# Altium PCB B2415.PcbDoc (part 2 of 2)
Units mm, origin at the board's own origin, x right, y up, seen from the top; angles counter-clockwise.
Board outline 20.32 x 48.65 mm, 4 copper layers (Top Layer, Internal 1, Internal 2, Bottom Layer), stack 0.62 mm thick; 96 components, 71 nets, 432 pads, 386 vias.
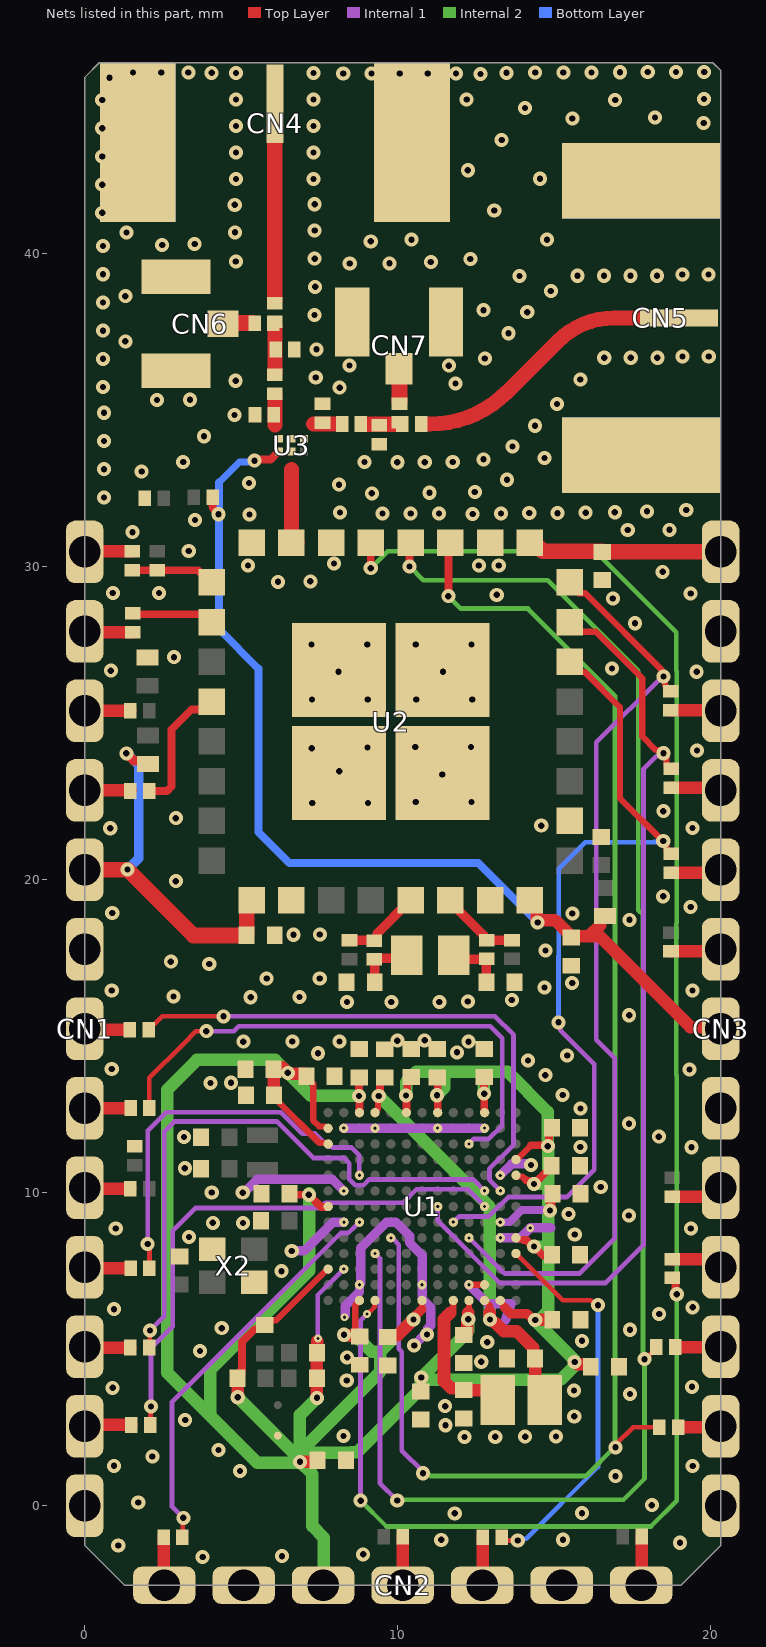
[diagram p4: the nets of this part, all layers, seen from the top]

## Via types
v1: diameter 0.45, hole 0.2, Top Layer to Bottom Layer, tented both sides, 351 vias
v2: diameter 0.25, hole 0.1, Top Layer to Internal 1, tented top, 35 vias

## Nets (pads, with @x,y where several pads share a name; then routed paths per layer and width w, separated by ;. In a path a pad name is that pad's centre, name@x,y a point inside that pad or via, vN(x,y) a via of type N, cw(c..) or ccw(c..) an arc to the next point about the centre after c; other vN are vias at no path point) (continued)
GND: C1.1 C2.1 C3.1 C4.1 C6.2 C7.1 C8.2 C9.2 C10.1 C17.1 C18.1 C19.1 C20.1 C21.1 C22.1 C23.1 C24.1 C25.1 C26.1 C27.1 C29.1 C30.1 C31.1 C38.1 C39.1 C40.1 C41.1 C42.1 C43.1 C44.1 C45.1 C46.1 CN1.6 CN1.13 CN2.2 CN2.6 CN3.1 CN3.6 CN3.12 CN4.2 CN4.3 CN4.4 CN4.5 CN5.2 CN5.3 CN5.4 CN5.5 CN6.2 CN6.3 CN7.2 CN7.3 R19.2 R30.1 R37.1 R38.1 R45.1 R46.1 R51.1 SB38.2 U1.B2 U1.B4 U1.B8 U1.B11 U1.E12 U1.F2 U1.H2 U1.J12 U1.M3 U1.M7 U1.M10 U1.M11 U2.10 U2.15 U2.18 U2.26 U2.30 U2.32 U2.33 U2.34 U2.35 U2.36 U3.2 X2.2 X2.4 | length 24.1
  Top Layer w0.2: U1.M10@12.293,7.038 12.317,7.062 U1.M11@12.778,7.062
  Internal 1 w0.3: v1@5.07,10.074 5.111,10.033 5.119,10.033 5.517,10.432 7.908,10.432 v2(8.276,10.064) ; v1(6.614,8.144) 7.013,8.144 7.931,9.062 v2(8.28,9.062) ; v2(8.276,12.066) 12.759,12.066 v2@12.761,12.068 ; v2@8.327,6.09 8.327,6.38 8.779,6.831 v2(8.779,7.063) 8.825,7.11 8.825,8.243 9.642,9.061 9.943,9.061 10.383,8.621 10.383,8.4 10.787,7.996 10.787,6.616 11.057,6.346 11.057,5.76 10.963,5.666 10.963,5.504 v1(10.934,5.476) 10.905,5.447 10.845,5.447 10.527,5.129 v1(10.527,5.124) ; v2(12.273,7.062) 12.878,6.457 13.626,6.457 13.442,5.923 ; v2(13.276,10.559) 13.642,10.925 v1@14.29,10.925 ; v2(13.28,8.564) 13.923,8.564 v2(14.238,8.879) 14.896,8.879
  other v1: 3.769,-1.639 6.303,-1.611 8.895,-1.552 1.071,-1.269 19.022,-1.182 11.393,-1.087 15.284,-1.086 11.824,-0.242 15.893,-0.237 18.12,0.02 1.709,0.102 16.959,0.945 4.964,1.111 0.938,1.277 19.425,1.273 2.161,1.573 4.273,1.779 12.132,2.201 13.118,2.202 14.074,2.209 15.059,2.21 8.27,2.233 11.531,2.573 3.209,2.741 15.643,2.857 11.516,3.182 17.425,3.57 15.633,3.683 0.894,3.769 19.408,3.8 8.373,4.001 12.67,4.601 8.385,4.744 3.681,4.948 12.863,5.229 15.891,5.269 17.421,5.624 4.379,5.674 18.355,6.126 0.932,6.281 19.426,6.342 6.287,7.495 3.331,8.59 15.657,8.667 0.992,8.863 19.367,8.862 4.093,9.041 5.055,9.038 17.385,9.272 15.463,9.32 5.049,10.005 4.059,10.011 16.488,10.189 3.198,10.786 14.26,10.887 15.835,11.461 19.386,11.456 3.175,11.783 18.344,11.795 17.388,12.21 15.839,12.693 15.271,13.126 4.018,13.507 4.67,13.518 14.719,13.759 19.321,13.941 0.864,13.957 14.16,14.231 15.416,14.386 7.452,14.46 11.897,14.488 5.068,14.831 8.144,14.834 12.261,14.829 6.635,14.837 9.988,14.862 10.863,14.874 17.396,15.674 8.38,16.099 9.797,16.094 11.331,16.099 12.241,16.113 13.646,16.159 5.303,16.249 2.833,16.277 6.86,16.257 0.864,16.467 19.417,16.467 14.695,16.563 15.574,16.705 5.814,16.85 7.509,16.849 3.978,17.313 2.752,17.387 14.724,17.741 6.669,18.246 7.513,18.251 17.408,18.723 0.879,18.942 15.579,18.925 19.361,19.133 18.482,19.473 2.911,19.957 0.815,21.65 19.42,21.654 14.588,21.731 2.91,21.972 18.488,22.194 7.267,22.458 9.052,22.458 10.577,22.487 12.362,22.487 11.428,23.37 8.133,23.467 19.564,24.136 7.253,24.207 9.033,24.227 10.56,24.247 12.345,24.247 7.261,25.763 9.046,25.763 10.594,25.763 12.379,25.763 8.112,26.646 11.445,26.646 19.553,26.65 0.835,26.685 16.846,26.757 2.855,27.116 7.244,27.524 9.029,27.524 10.577,27.524 12.362,27.524 17.583,28.199 16.876,28.99 13.164,29.107 19.361,29.149 0.897,29.163 2.371,29.164 6.175,29.522 7.208,29.538 18.467,29.843 5.22,30.042 12.592,30.049 13.229,30.045 7.967,30.109 3.323,30.51 1.527,31.109 17.352,31.182 18.684,31.185 3.525,31.502 5.268,31.677 12.395,31.689 9.515,31.709 10.416,31.709 11.317,31.709 13.303,31.707 14.204,31.719 15.105,31.718 8.16,31.735 16.007,31.734 16.938,31.746 17.965,31.775 19.219,31.821 0.619,32.222 9.174,32.351 11.017,32.37 12.464,32.393 8.125,32.629 5.249,32.683 13.489,32.786 1.819,33.05 0.619,33.123 8.938,33.349 9.988,33.344 10.864,33.347 3.145,33.356 11.76,33.355 12.744,33.436 14.692,33.477 13.672,33.851 0.619,34.024 3.812,34.176 14.388,34.51 4.788,34.852 0.619,34.925 15.091,35.208 2.307,35.331 3.366,35.342 8.146,35.728 0.586,35.746 11.85,35.86 4.823,35.947 15.837,35.985 7.383,36.051 8.461,36.435 11.634,36.429 0.586,36.648 12.784,36.659 16.601,36.684 17.448,36.684 18.296,36.684 19.101,36.723 19.939,36.724 7.403,36.952 1.298,37.208 13.538,37.467 0.586,37.549 7.342,38.047 14.14,38.14 12.741,38.203 0.586,38.45 1.298,38.65 14.894,38.814 7.362,38.948 13.891,39.299 15.747,39.304 16.594,39.304 17.442,39.304 18.289,39.304 19.094,39.343 19.932,39.344 0.586,39.351 8.469,39.694 9.739,39.699 11.059,39.742 4.828,39.757 7.347,39.849 12.321,39.84 0.586,40.253 2.475,40.289 3.511,40.317 9.14,40.402 10.443,40.455 14.772,40.456 1.336,40.688 4.803,40.69 7.347,40.751 0.56,41.313 13.085,41.386 4.794,41.571 7.346,41.588 0.56,42.215 4.832,42.392 7.307,42.393 14.548,42.404 12.242,42.675 0.56,43.116 4.832,43.239 7.307,43.241 13.323,43.645 0.56,44.017 4.832,44.086 7.307,44.088 19.778,44.181 15.582,44.329 18.222,44.361 14.071,44.663 0.56,44.919 16.95,44.917 4.832,44.934 7.307,44.935 12.204,44.937 19.786,44.953 0.795,45.632 8.26,45.763 9.161,45.763 10.063,45.763 10.964,45.763 11.865,45.763 12.649,45.751 4.055,45.787 4.832,45.781 7.307,45.783 13.48,45.788 1.543,45.797 2.444,45.797 3.311,45.799 14.392,45.801 15.293,45.801 16.195,45.801 17.101,45.807 17.991,45.811 18.893,45.811 19.794,45.811
  other v2: 8.297,6.024 10.777,7.063 9.275,12.062 11.278,12.066 12.777,12.066
JTCK: R9.2 U2.2 | length 2.7
  Top Layer w0.25: R9.2@1.443,28.489 3.755,28.489 U2.2@4.031,28.213
JTDI: R11.2 U2.4 | length 4.1
  Top Layer w0.25: R11.2@2.057,22.84 2.631,22.84 2.777,22.986 2.777,24.808 3.418,25.448 3.891,25.448 U2.4@3.994,25.551
JTMS: R8.2 R34.1 U2.1 | length 2.7
  Top Layer w0.25: R8.2@1.521,29.895 3.618,29.895 3.708,29.804 3.764,29.804 4.031,29.538 U2.1@4.031,29.483
LPUART1_RX: R2.1 U1.G8 U2.23 | length 30.9
  Top Layer w0.2: U2.23@15.461,28.213 15.749,27.924 16.333,27.924 17.813,26.444 17.813,24.585 18.253,24.146 18.325,24.146 18.426,24.045 v1(18.494,24.045) 18.494,23.977 18.588,23.883 18.588,23.647 18.714,23.522 R2.1@18.762,23.522
  Internal 1 w0.15: v2(11.28,9.562) 11.28,9.106 13.269,7.117 16.638,7.117 17.857,8.335 17.857,23.545 18.258,23.945 18.313,23.945 18.413,24.045 v1(18.494,24.045)
"LPUART1_TX/ HostWakeup": R3.1 U1.H9 U2.22 | length 26.6
  Top Layer w0.2: U2.22@15.461,26.943 15.762,26.642 15.972,26.642 17.102,25.512 17.102,22.604 18.463,21.243 v1(18.486,21.243) 18.486,21.175 18.59,21.071 18.59,20.929 18.657,20.862 R3.1@18.753,20.862
  Internal 1 w0.15: v2@11.806,9.086 11.966,9.246 12.914,9.246 13.533,9.864 15.407,9.864 16.282,10.739 16.282,14.114 15.197,15.198 15.197,15.389 v1(15.14,15.446)
  Bottom Layer w0.15: v1(15.14,15.446) 15.14,17.563 15.144,17.567 15.144,20.361 15.987,21.205 18.172,21.205 18.18,21.213 18.456,21.213 v1(18.486,21.243)
  other v2: 11.776,9.065
NetC6_1: C6.1 R22.2 X3.2 | length 1.7
  Top Layer w0.3: R22.2@9.248,17.46 9.281,17.493 10.284,17.493 X3.2@10.294,17.502 ; C6.1@9.267,16.729 9.267,17.41 R22.2@9.271,17.41
NetC7_2: C7.2 R23.2 X3.1 | length 1.9
  Top Layer w0.3: X3.1@11.793,17.593 11.919,17.466 R23.2@12.845,17.466 ; C7.2@12.832,16.734 12.832,17.423 12.854,17.444 R23.2@12.916,17.444
NetC40_2: C40.2 L1.1 U1.N9 | length 4.3
  Top Layer w0.2: 11.678,6.165 11.778,6.265 U1.N9@11.778,6.562
  Top Layer w0.3: L1.1@12.872,3.692 L1.1@12.923,3.641
  Top Layer w0.4: 11.678,6.165 11.48,5.966 11.48,3.984 11.714,3.75 12.058,3.75 12.115,3.692 L1.1@12.872,3.692
NetC44_2: C44.2 C45.2 L1.2 U1.A4 U1.N11 | length 13.9
  Top Layer w0.2: U1.A4@9.278,12.562 9.278,12.589 9.369,12.68 v1@9.369,13.095 ; U1.N11@12.778,6.562 12.948,6.392 12.948,6.185
  Top Layer w0.25: v1@9.395,13.149 9.434,13.188 9.434,13.557 9.55,13.673 C45.2@9.612,13.673
  Top Layer w0.4: v1(12.948,5.955) 12.948,6.185 ; v1@13.108,5.855 13.383,5.579 13.804,5.579 14.339,5.044 14.339,4.761 C44.2@14.394,4.706 14.394,3.685 L1.2@14.698,3.381
  Internal 2 w0.4: v1(9.395,13.095) 12.948,9.541 v1(12.948,5.955)
NetCN1_1: CN1.1 R8.1 | length 1.5
  Top Layer w0.4: CN1.1@0.015,30.495 R8.1@1.521,30.495
NetCN1_2: CN1.2 R9.1 | length 1.5
  Top Layer w0.4: CN1.2@0.025,27.915 R9.1@1.532,27.915
NetCN1_3: CN1.3 R10.1 | length 1.5
  Top Layer w0.25: R10.1@1.455,25.4 R10.1@1.474,25.419
  Top Layer w0.4: CN1.3@0,25.4 R10.1@1.455,25.4
NetCN1_4: CN1.4 R11.1 | length 1.5
  Top Layer w0.25: R11.1@1.467,22.86 R11.1@1.497,22.83
  Top Layer w0.4: CN1.4@0,22.86 R11.1@1.467,22.86
NetCN1_7: CN1.7 R12.1 | length 1.3
  Top Layer w0.25: CN1.7@0.146,15.185 CN1.7@0.172,15.211
  Top Layer w0.4: CN1.7@0.172,15.211 R12.1@1.445,15.211
NetCN1_8: CN1.8 R13.1 | length 1.3
  Top Layer w0.3: CN1.8@0.202,12.711 CN1.8@0.204,12.708
  Top Layer w0.4: CN1.8@0.204,12.708 R13.1@1.464,12.708
NetCN1_9: CN1.9 R14.1 | length 1.2
  Top Layer w0.3: CN1.9@0.304,10.144 CN1.9@0.313,10.134
  Top Layer w0.4: CN1.9@0.313,10.134 R14.1@1.457,10.134
NetCN1_10: CN1.10 R15.1 | length 1.3
  Top Layer w0.3: CN1.10@0.174,7.586 CN1.10@0.181,7.593
  Top Layer w0.4: CN1.10@0.181,7.593 R15.1@1.469,7.593
NetCN1_11: CN1.11 R16.1 | length 1.4
  Top Layer w0.3: CN1.11@0.063,5.047 CN1.11@0.072,5.056
  Top Layer w0.4: CN1.11@0.072,5.056 R16.1@1.459,5.056
NetCN1_12: CN1.12 R17.1 | length 1.4
  Top Layer w0.25: R17.1@1.485,2.582 R17.1@1.488,2.579
  Top Layer w0.4: CN1.12@0.044,2.582 R17.1@1.485,2.582
NetCN2_1: CN2.1 R20.1 | length 1.6
  Top Layer w0.4: CN2.1@2.521,-2.618 R20.1@2.521,-0.983
NetCN2_4: CN2.4 R21.1 | length 1.6
  Top Layer w0.4: CN2.4@10.143,-2.573 10.159,-2.556 R21.1@10.159,-0.987
NetCN2_5: CN2.5 R28.1 | length 1.5
  Top Layer w0.4: CN2.5@12.72,-2.478 R28.1@12.72,-0.98
NetCN2_7: CN2.7 R27.1 | length 1.5
  Top Layer w0.4: R27.1@17.792,-0.981 17.792,-2.469 CN2.7@17.834,-2.511
NetCN3_2: CN3.2 R26.2 | length 1.4
  Top Layer w0.4: R26.2@18.984,2.515 20.342,2.515 CN3.2@20.351,2.523
NetCN3_3: CN3.3 R7.2 | length 1.6
  Top Layer w0.4: R7.2@18.865,5.071 20.396,5.071 CN3.3@20.413,5.054
NetCN3_4: CN3.4 R6.2 | length 1.7
  Top Layer w0.4: R6.2@18.779,7.88 19.965,7.88 CN3.4@20.347,7.499
NetCN3_5: CN3.5 R5.2 | length 1.6
  Top Layer w0.4: R5.2@18.77,9.877 19.948,9.877 CN3.5@20.281,10.21
NetCN3_8: CN3.8 R4.2 | length 1.6
  Top Layer w0.25: CN3.8@20.292,17.717 CN3.8@20.33,17.755
  Top Layer w0.4: R4.2@18.733,17.717 CN3.8@20.292,17.717
NetCN3_9: CN3.9 R3.2 | length 1.5
  Top Layer w0.25: CN3.9@20.165,20.229 CN3.9@20.199,20.263
  Top Layer w0.4: R3.2@18.74,20.229 CN3.9@20.165,20.229
NetCN3_10: CN3.10 R2.2 | length 1.6
  Top Layer w0.25: CN3.10@20.223,22.947 CN3.10@20.299,22.872
  Top Layer w0.4: R2.2@18.738,22.947 CN3.10@20.223,22.947
NetCN3_11: CN3.11 R1.2 | length 1.6
  Top Layer w0.25: CN3.11@20.352,25.426 CN3.11@20.368,25.442
  Top Layer w0.4: R1.2@18.731,25.426 CN3.11@20.352,25.426
NetCN4_1: CN4.1 R49.2 | length 6.3
  Top Layer w0.5: R49.2@6.076,38.5 6.076,44.783 6.076,44.786 6.076,44.794 CN4.1@6.076,44.798
NetCN5_1: CN5.1 R50.2 | length 9.3
  Top Layer w0.48: R50.2@10.818,34.567 11.036,34.567 ccw(c11.036,38.034) 13.489,35.583 15.119,37.213 cw(c16.915,35.417) 16.915,37.957 18.99,37.957 CN5.1@18.991,37.956
NetCN6_1: CN6.1 R39.1 | length 1
  Top Layer w0.5: CN6.1@4.428,37.792 R39.1@5.357,37.792
  Top Layer w0.52: CN6.1@4.395,37.826 CN6.1@4.428,37.792
NetCN7_1: CN7.1 R47.1 | length 1.1
  Top Layer w0.5: CN7.1@10.043,36.328 10.042,36.327 10.057,36.311 R47.1@10.057,35.282
NetJ?_S1: 
NetR22_1: R22.1 R31.2 U2.13 | length 2.4
  Top Layer w0.3: R31.2@8.459,18.068 9.226,18.068 R22.1@9.249,18.045 ; R22.1@9.348,18.11 9.348,18.291 U2.13@10.381,19.323
NetR23_1: R23.1 R32.1 U2.14 | length 2.4
  Top Layer w0.3: U2.14@11.651,19.323 R23.1@12.745,18.229 ; R23.1@12.845,18.073 13.639,18.073 R32.1@13.667,18.101
Red_LED_U5: R28.2 U1.K13 | length 12.6
  Top Layer w0.15: R28.2@13.298,-1.014 13.397,-1.112 v1(13.835,-1.112) ; U1.K13@13.778,8.062 15.272,6.568 16.163,6.568 16.32,6.411 v1(16.401,6.411)
  Bottom Layer w0.15: v1(13.835,-1.112) 13.893,-1.055 14.106,-1.055 16.401,1.239 v1(16.401,6.411)
RF1: R36.1 R37.2 U3.3 | length 1
  Top Layer w0.24: R36.1@6.077,35.532 R36.1@6.081,35.536
  Top Layer w0.48: R36.1@6.076,35.479 6.077,34.857 6.077,34.531
RF1b: R36.2 R38.2 R39.2 R49.1 | length 1.5
  Top Layer w0.48: R36.2@6.079,36.182 6.079,36.941 R49.1@6.079,37.685
RF2: R44.1 R45.2 U3.1 | length 0.9
  Top Layer w0.48: 7.309,34.565 R44.1@8.171,34.565
RF2b: R44.2 R46.2 R47.2 R50.1 | length 1.2
  Top Layer w0.5: R44.2@8.899,34.563 9.414,34.563 R50.1@10.084,34.563
RF_Pin: U2.31 U3.5 | length 2.4
  Top Layer w0.48: U2.31@6.604,30.774 6.604,33.111
  Top Layer w0.8: U2.31@6.604,30.774 U2.31@6.629,30.799
RSTN: R20.2 U1.H3 | length 12.9
  Top Layer w0.15: R20.2@3.119,-1.005 3.128,-0.996 3.128,-0.397 v1@3.147,-0.377
  Internal 1 w0.15: v1(3.149,-0.384) 2.789,-0.024 2.789,3.328 8.178,8.717 8.423,8.717 8.625,8.919 8.625,8.92 8.763,9.058 v2(8.781,9.058)
SPI_CLK_U5: R7.1 U1.K4 U2.28 | length 52.3
  Top Layer w0.15: U2.28@10.381,30.754 U2.28@10.412,30.784 ; v1(17.887,4.684) 17.912,4.684 18.124,4.896 18.14,4.896 18.265,5.021 R7.1@18.265,5.071
  Top Layer w0.25: v1(10.381,30.015) U2.28@10.381,30.754
  Internal 1 w0.15: v2(9.277,8.061) 9.433,7.905 9.433,0.722 v1(9.987,0.168)
  Internal 2 w0.15: v1@9.961,0.188 17.215,0.188 17.887,0.859 17.887,4.726 17.841,4.772 17.841,18.884 17.69,19.035 17.69,26.684 14.796,29.577 10.819,29.577 v1(10.381,30.015)
SPI_CS_U5: R1.1 U1.J10 U2.24 | length 29.7
  Top Layer w0.2: U2.24@15.461,29.483 15.462,29.483 15.787,29.158 15.987,29.158 18.446,26.699 18.446,26.543 18.542,26.447 18.542,26.222 18.581,26.183 18.581,26.126 18.671,26.036 R1.1@18.727,26.036
  Internal 1 w0.15: v2(12.279,8.56) 13.419,7.42 15.807,7.42 16.933,8.546 16.933,14.305 16.347,14.891 16.347,24.39 18.452,26.495 v1(18.494,26.495)
"SPI_MISO_U5 / JTDO": R6.1 U1.N4 U2.29 | length 57.6
  Top Layer w0.15: v2(9.019,6.132) 9.043,6.132 9.259,6.348 U1.N4@9.259,6.556 ; U2.29@9.111,30.753 9.139,30.782 U2.29@9.174,30.817
  Top Layer w0.25: v1(9.139,29.961) U2.29@9.139,30.782 ; R6.1@18.841,7.268 18.879,7.23 18.879,6.796 v1(18.917,6.758)
  Internal 1 w0.15: v1(8.817,0.163) 8.814,0.166 8.814,5.927 v2(9.019,6.132)
  Internal 2 w0.15: v1(8.817,0.163) 9.643,-0.662 18.092,-0.662 18.917,0.163 v1@18.917,6.748 ; v1(9.139,29.961) 9.676,30.498 16.312,30.498 18.901,27.909 18.901,26.682 18.914,26.669 18.914,18.611 18.901,18.598 18.901,13.767 18.917,13.751 v1(18.917,6.758)
SPI_MOSI_U5: R26.1 U1.J5 U2.27 | length 48.5
  Top Layer w0.15: v1(16.957,1.867) 16.957,1.948 17.52,2.511 18.25,2.511 R26.1@18.254,2.515
  Top Layer w0.25: v1(11.62,29.066) 11.623,29.07 U2.27@11.623,30.772
  Internal 1 w0.15: v2(9.784,8.56) 9.811,8.56 9.861,8.51 9.872,8.51 10.038,8.344 10.038,5.019 10.133,4.924 10.133,1.76 10.812,1.081 v1(10.812,1.038)
  Internal 2 w0.15: v1(10.812,1.038) 10.87,0.981 11.019,0.981 11.05,0.949 16.013,0.949 16.944,1.88 16.944,25.886 14.162,28.668 12.018,28.668 v1(11.62,29.066)
SWCLK: R13.2 U1.C10 | length 17.2
  Top Layer w0.15: R13.2@2.064,12.708 2.064,13.674 3.144,14.754 3.551,15.161 3.881,15.161 v1(3.884,15.164)
  Internal 1 w0.15: v1(3.884,15.164) 4.766,15.164 4.925,15.324 12.955,15.324 13.341,14.938 13.341,12.149 12.913,11.721 12.43,11.721 v2(12.275,11.565)
SWDIO: R12.2 U1.F12 | length 17.6
  Top Layer w0.15: R12.2@2.045,15.211 2.045,15.261 2.17,15.386 2.22,15.386 2.475,15.641 v1(4.436,15.641)
  Internal 1 w0.15: v1(4.436,15.641) 13.107,15.641 13.702,15.045 13.702,11.535 12.931,10.764 12.931,10.414 v2(13.28,10.065)
USER_Buttom_U5: R15.2 U1.E3 | length 12.6
  Top Layer w0.15: v1(2.011,8.366) 2.011,8.285 2.069,8.227 R15.2@2.069,7.593
  Internal 1 w0.15: v1(2.011,8.366) 2.011,11.989 2.598,12.576 6.27,12.576 6.953,11.893 7.359,11.893 7.784,11.467 7.909,11.467 7.929,11.447 8.527,11.447 8.775,11.2 v2(8.775,10.56)
VCP1_RX: R16.2 U1.F11 | length 18.9
  Top Layer w0.15: R16.2@2.059,5.056 2.073,5.07 2.073,5.574 v1@2.092,5.594
  Internal 1 w0.15: v1@2.079,5.587 2.541,6.049 2.541,11.951 2.871,12.281 6.131,12.281 7.297,11.115 8.279,11.115 8.455,10.94 8.455,10.427 8.642,10.24 8.907,10.24 9.095,10.427 12.411,10.427 v2(12.774,10.065)
  other v1: 2.086,5.601
VCP1_TX: R17.2 U1.G11 | length 17.3
  Top Layer w0.15: R17.2@2.088,2.579 2.102,2.593 2.102,3.159 v1@2.121,3.178
  Internal 1 w0.15: v1(2.116,3.175) 2.116,5.037 2.811,5.731 2.811,8.787 3.538,9.514 7.315,9.514 7.318,9.517 7.517,9.517 7.682,9.682 10.172,9.682 10.601,10.111 12.232,10.111 v2(12.778,9.566)
VDD33: C10.2 CN3.7 R33.2 R52.2 U2.16 U3.4 | length 33.9
  Top Layer w0.25: R52.2@4.083,32.222 4.083,31.976 ccw(c4.333,31.976) v1@4.158,31.797 ; v1@4.159,31.796 v1(4.277,31.681) ; v1(5.424,33.394) 5.462,33.432 5.942,33.432 U3.4@6.203,33.693
  Top Layer w0.4: U2.16@14.191,19.323 14.246,19.323 14.449,19.119 14.449,18.673 14.471,18.651 v1(14.471,18.638) 14.485,18.638 14.56,18.712 15.022,18.712 15.468,18.266 15.468,18.21 15.479,18.199 15.548,18.199 16.119,18.199 ; R33.2@16.647,18.864 16.549,18.864 16.47,18.784 16.47,18.549 16.119,18.199 ; CN3.7@20.32,15.24 20.265,15.295 19.354,15.295 16.45,18.199 16.119,18.199
  Bottom Layer w0.22: 4.295,32.698 4.947,33.35 5.38,33.35 v1(5.424,33.394)
  Bottom Layer w0.25: 4.295,32.698 4.295,28.003 5.548,26.751 5.548,21.528 6.539,20.537 12.572,20.537 v1(14.471,18.638)
VDD_IO1: C8.1 CN1.5 R29.2 U2.9 | length 11.9
  Top Layer w0.3: v1@1.398,23.976 1.563,23.811 1.922,23.811 R29.2@2.027,23.706
  Top Layer w0.5: CN1.5@0,20.32 v1@1.361,20.32 ; v1(1.37,20.328) 3.474,18.224 C8.1@5.15,18.224 ; C8.1@5.171,18.227 5.171,19.209 U2.9@5.257,19.295
  Bottom Layer w0.3: v1@1.336,24.06 1.722,23.674 1.722,20.681 v1(1.37,20.328)
  other v1: 1.328,24.043
VDD_IO2: C9.1 CN3.13 U2.25 | length 6
  Top Layer w0.5: U2.25@14.169,30.777 14.344,30.602 14.537,30.602 14.637,30.503 C9.1@16.553,30.503 ; C9.1@16.813,30.48 CN3.13@20.32,30.48
VDD_MCU: C17.2 C18.2 C19.2 C20.2 C21.2 C22.2 C23.2 C24.2 C25.2 C26.2 C27.2 C29.2 C30.2 C31.2 C33.2 C34.2 C35.2 C36.2 C38.2 C39.2 C41.2 C42.2 C43.2 CN2.3 U1.A3 U1.A6 U1.A8 U1.A11 U1.B1 U1.C1 U1.D13 U1.E13 U1.G1 U1.H12 U1.J13 U1.L1 U1.L2 U1.N3 U1.N7 U1.N10 U1.N12 | length 111.9
  Top Layer w0.2: C34.2@5.777,5.772 5.932,5.927 6.12,5.927 7.755,7.562 U1.L1@7.778,7.562 ; C39.2@6.114,12.979 7.501,11.591 7.678,11.591 7.688,11.581 7.759,11.581 U1.C1@7.778,11.562 ; C27.2@7.08,13.732 7.08,13.707 7.301,13.486 7.301,12.309 7.488,12.122 7.691,12.122 7.751,12.062 U1.B1@7.778,12.062 ; U1.N3@8.778,6.562 8.778,6.535 8.642,6.399 8.642,5.549 C21.2@8.786,5.406 ; 10.778,6.282 U1.N7@10.778,6.562 ; 12.267,6.26 12.278,6.272 U1.N10@12.278,6.562 ; U1.N12@13.278,6.562 13.278,6.535 13.418,6.394 13.418,6.328 ; U1.J13@13.778,8.562 13.805,8.562 13.858,8.509 14.002,8.509 14.015,8.495 ; U1.D13@13.778,11.062 13.805,11.062 14.264,11.521 ; U1.E13@13.795,10.581 13.795,10.572 13.824,10.543 13.833,10.543 13.853,10.523 13.985,10.523 14.077,10.431
  Top Layer w0.25: C33.2@4.878,4.073 5.008,4.203 5.008,4.361 5.021,4.374 5.021,5.232 5.432,5.642 5.653,5.642 C34.2@5.777,5.765 ; C22.2@6.519,9.917 6.539,9.937 v1(7.16,9.937) 7.548,9.548 U1.G1@7.74,9.548 ; v1(8.765,13.097) 8.767,13.099 8.767,13.592 C20.2@8.806,13.631 ; U1.A3@8.778,12.562 v1@8.778,13.067 ; v1(10.266,13.112) 10.304,13.15 10.304,13.579 C31.2@10.414,13.689 ; U1.A6@10.278,12.562 v1@10.278,13.058 ; U1.A8@11.278,12.562 11.278,13.694 C25.2@11.282,13.698 ; U1.A11@12.794,12.566 12.787,12.566 12.768,12.585 12.768,12.592 12.764,12.597 v1(12.764,13.168) 12.761,13.17 12.761,13.584 C26.2@12.862,13.685 ; 14.015,8.495 14.112,8.495 v1@14.275,8.331 ; 14.077,10.431 14.123,10.384 v1@14.204,10.384 ; 14.264,11.521 v1@14.797,11.521 ; v1(14.358,8.284) 14.651,7.99 C24.2@14.686,7.99 ; v1(14.358,10.284) 14.781,10.708 14.824,10.708 C38.2@14.922,10.806 ; v1(14.798,11.492) 14.836,11.53 14.836,12.106 C19.2@14.87,12.14
  Top Layer w0.3: v1(10.508,5.953) 10.508,5.993 10.583,6.068 10.583,6.087 10.778,6.282 ; C43.2@12.113,5.461 12.121,5.461 C43.2@12.226,5.566 ; v1@12.226,5.931 v1(12.255,5.96) ; 13.418,6.328 13.604,6.142 14.136,6.142 14.268,6.01 14.28,6.01 v1@14.326,5.963 ; v1(14.864,9.435) 14.893,9.464 14.893,9.956 C30.2@14.891,9.958
  Top Layer w0.4: C33.2@4.847,4.071 4.884,4.034 4.884,3.473 v1(4.89,3.466) ; C41.2@6.038,13.953 6.045,13.946 6.045,13.148 C39.2@6.065,13.128 ; C41.2@6.079,13.888 6.093,13.902 6.093,13.959 C41.2@6.178,13.959 ; 6.308,14.015 v1@6.379,13.943 ; v1(6.49,13.834) 6.488,13.834 v1@6.379,13.943 ; v1(6.878,1.404) 6.888,1.414 7.389,1.414 7.421,1.445 C17.2@7.421,1.463 ; C27.2@7.053,13.68 7.053,13.784 7.025,13.812 6.51,13.812 v1@6.379,13.943 ; C35.2@7.418,4.071 7.42,4.073 C36.2@7.42,4.891 ; v1(7.42,3.45) C35.2@7.42,4.068 ; C36.2@7.422,4.891 7.437,4.906 v2@7.437,5.257 ; v1(8.285,5.465) 8.294,5.456 8.706,5.456 8.756,5.406 C21.2@8.786,5.406 ; C23.2@9.679,5.386 9.734,5.441 9.996,5.441 v1(10.508,5.953) ; C43.2@12.226,5.566 v1@12.226,5.931 ; v1(12.255,5.96) v1@12.255,6.169 ; v1@14.393,5.95 14.404,5.939 14.934,5.939 C18.2@14.938,5.943 ; v1(15.656,4.592) 15.669,4.592 15.732,4.529 16.113,4.529 16.147,4.495 C29.2@16.147,4.445
  Internal 1 w0.15: v2(7.449,5.348) 7.449,6.735 v2(8.277,7.563)
  Internal 1 w0.25: v2(13.277,9.059) 13.575,9.059 13.97,9.454 14.845,9.454 v1(14.864,9.435)
  Internal 2 w0.4: v1(4.89,3.466) 6.757,1.6 ; v1@6.878,1.368 5.517,1.368 4.011,2.874 ; 6.878,1.721 6.878,2.907 v1(7.42,3.45) ; v1@6.878,1.57 6.878,1.721 9.45,4.294 9.45,4.923 9.456,4.929 ; v1@7.177,9.989 7.169,9.982 7.169,9.946 v1(7.16,9.937) 7.16,9.923 7.177,9.906 7.177,7.513 4.011,4.348 4.011,2.874 ; CN2.3@7.636,-2.502 7.636,-1.017 7.271,-0.652 7.271,1.012 v1(6.878,1.404) 7.162,1.688 8.496,1.688 8.522,1.714 8.708,1.714 10.742,3.749 10.742,4.089 v1(10.752,4.099) ; v1@8.298,5.465 8.308,5.456 8.643,5.456 9.17,4.929 9.456,4.929 ; v1(8.765,13.097) 7.228,13.097 v1(6.49,13.834) 6.08,14.245 3.587,14.245 2.631,13.289 2.631,12.01 2.63,12.009 2.63,11.558 2.631,11.557 2.631,4.254 4.011,2.874 ; v1(10.266,13.112) 10.266,13.54 10.595,13.869 11.48,13.869 ; v1@10.485,5.943 10.469,5.928 10.455,5.928 9.456,4.929 ; v1@10.775,4.089 10.844,4.02 15.199,4.02 15.646,4.467 15.646,4.582 v1(15.656,4.592) 15.646,4.601 15.646,4.666 v1@14.436,5.876 ; v1@10.791,4.124 12.258,5.591 12.258,5.958 v1(12.255,5.96) ; v1(11.26,13.116) 11.26,13.13 11.48,13.35 11.48,13.869 ; v1@12.754,13.188 12.754,13.869 ; v1(14.358,8.284) 14.781,8.284 14.808,8.31 ; v1(14.358,10.284) 14.364,10.29 14.714,10.29 ; v1@14.523,5.944 14.808,6.228 14.808,8.31 ; v1@14.788,11.538 14.788,12.59 13.509,13.869 12.754,13.869 ; v1@14.789,11.496 v1@14.789,11.537 ; v1@14.808,11.463 14.808,9.505 14.864,9.448 v1(14.864,9.435) 14.864,9.421 14.808,9.365 14.808,8.31 ; 11.48,13.869 12.754,13.869
  other v1: 14.396,5.935
pads on no net: CART-1.1 U1.A1 U1.A2 U1.A5 U1.A7 U1.A9 U1.A10 U1.A12 U1.A13 U1.B3 U1.B5 U1.B6 U1.B7 U1.B9 U1.B10 U1.B12 U1.B13 U1.C2 U1.C3 U1.C4 U1.C6 U1.C7 U1.C8 U1.C9 U1.C11 U1.C12 U1.C13 U1.D2 U1.D3 U1.D4 U1.D5 U1.D6 U1.D7 U1.D8 U1.D9 U1.D10 U1.D11 U1.D12 U1.E2 U1.E4 U1.E5 U1.E6 U1.E7 U1.E8 U1.E9 U1.E10 U1.E11 U1.F1 U1.F3 U1.F4 U1.F5 U1.F6 U1.F7 U1.F8 U1.F9 U1.F10 U1.F13 U1.G2 U1.G3 U1.G4 U1.G5 U1.G6 U1.G7 U1.G9 U1.G10 U1.G12 U1.G13 U1.H4 U1.H5 U1.H6 U1.H7 U1.H8 U1.H10 U1.H11 U1.H13 U1.J2 U1.J3 U1.J4 U1.J6 U1.J8 U1.J9 U1.K1 U1.K3 U1.K5 U1.K6 U1.K7 U1.K8 U1.K9 U1.K10 U1.K11 U1.K12 U1.L3 U1.L4 U1.L5 U1.L6 U1.L7 U1.L9 U1.L10 U1.L11 U1.L12 U1.L13 U1.M1 U1.M4 U1.M5 U1.M6 U1.M9 U1.M12 U1.M13 U1.N1 U1.N2 U1.N5 U1.N6 U1.N8 U1.N13 U2.5 U2.6 U2.7 U2.8 U2.11 U2.12 U2.19 U2.20
copper on no net: | length 1348.4
  Top Layer w0.381: 0.321,92.486 10.733,92.486 34.348,92.486 56.186,92.486 72.692,92.486 87.167,92.486 ; 0.321,95.534 10.733,95.534 34.348,95.534 56.186,95.534 72.692,95.534 87.167,95.534 ; 0.321,98.582 10.733,98.582 34.348,98.582 56.186,98.582 72.692,98.582 87.167,98.582 ; 0.321,101.63 10.733,101.63 34.348,101.63 56.186,101.63 72.692,101.63 87.167,101.63 ; 0.321,104.678 10.733,104.678 34.348,104.678 56.186,104.678 72.692,104.678 87.167,104.678 ; 0.321,107.726 10.733,107.726 34.348,107.726 56.186,107.726 72.692,107.726 87.167,107.726 ; 0.321,110.774 10.733,110.774 34.348,110.774 56.186,110.774 72.692,110.774 87.167,110.774 ; 0.321,113.822 10.733,113.822 34.348,113.822 56.186,113.822 72.692,113.822 87.167,113.822 ; 0.321,116.87 10.733,116.87 34.348,116.87 56.186,116.87 72.692,116.87 87.167,116.87 ; 0.321,119.918 10.733,119.918 34.348,119.918 56.186,119.918 72.692,119.918 87.167,119.918 ; 0.321,122.966 87.167,122.966 ; 10.733,126.014 10.733,89.438 ; 34.348,126.014 34.348,89.438 ; 56.186,126.014 56.186,89.438 ; 72.692,126.014 72.692,89.438 ; 10.733,89.438 34.348,89.438 ; 10.733,89.438 0.321,89.438 0.321,126.014 87.167,126.014 87.167,89.438 72.692,89.438 ; 34.348,89.438 56.186,89.438 ; 56.186,89.438 72.692,89.438

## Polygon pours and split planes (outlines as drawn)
GND on Internal 1 "GND_L02_P001" (solid, pour order 1): 0.003,45.653 0.207,45.862 0.466,46.112 20.053,46.112 20.31,45.859 20.31,-1.274 19.037,-2.539 1.262,-2.54 -0.009,-1.269 -0.005,45.645
GND on Internal 2 "GND_L03_P002" (solid, pour order 2): -0.038,45.645 0.166,45.853 0.425,46.104 20.012,46.104 20.269,45.85 20.269,-1.282 18.996,-2.547 1.221,-2.548 -0.05,-1.278 -0.046,45.636
GND on Bottom Layer "GND_L04_P003" (solid, pour order 3): 0.059,45.635 0.263,45.843 0.522,46.094 20.11,46.094 20.367,45.84 20.367,-1.292 19.094,-2.557 1.319,-2.558 0.048,-1.287 0.051,45.627
GND on Top Layer "GND_L01_P000" (solid, pour order 0): 0.039,45.621 0.243,45.829 0.502,46.08 20.089,46.08 20.346,45.827 20.346,-1.306 19.073,-2.571 1.298,-2.572 0.027,-1.301 0.031,45.613

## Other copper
Top Layer:
  pour cut-out: 10.728,37.127 10.728,35.64 10.485,35.494 9.644,35.494 9.383,35.652 9.383,37.127
  region net NetCN5_1: 17.349,38.198 17.742,38.231 17.742,37.681 17.35,37.718 17.349,38.198
  pour cut-out: 17.742,38.447 17.755,37.455 17.35,37.538 17.35,38.376 17.741,38.446
  pour cut-out: 5.588,43.542 6.579,43.555 6.505,43.166 5.647,43.164 5.589,43.541
  region net NetCN4_1: 5.802,43.546 6.351,43.549 6.325,43.166 5.827,43.166 5.802,43.547
  pour cut-out: 17.744,37.46 17.744,37.68 20.316,37.68 20.316,37.46
  pour cut-out: 17.742,38.23 17.742,38.45 20.314,38.45 20.314,38.23
  pour cut-out: 6.359,46.13 6.579,46.13 6.579,43.558 6.359,43.558
  pour cut-out: 5.588,46.114 5.808,46.114 5.808,43.542 5.588,43.542
  pour cut-out: 6.354,33.822 6.354,33.971 6.87,33.971 6.876,33.965 6.876,33.823
  pour cut-out: 6.328,34.495 6.477,34.495 6.477,33.978 6.471,33.973 6.33,33.973
  pour cut-out: 5.76,29.938 7.438,29.938 7.438,31.19 7.438,31.2 7.016,31.716 6.194,31.719 5.76,31.2
  region net NetCN7_1: 10.46,35.869 10.467,35.841 10.304,35.49 9.809,35.49 9.617,35.841 9.641,35.869
  pour cut-out: 3.634,38.456 5.121,38.456 5.267,38.213 5.267,37.372 5.109,37.111 3.634,37.111
  region net RF2: 6.878,34.182 6.878,34.217 7.102,34.687 7.364,34.687 7.364,34.334 7.127,34.211 7.127,34.182
  region net RF1: 6.077,34.17 6.078,34.172 6.078,34.214 6.077,34.212 5.93,34.342 6.102,34.513 6.313,34.513 6.327,34.214 6.327,34.173 6.326,34.172
  region net RF_Pin: 6.374,33.177 6.481,33.567 6.481,33.59 6.723,33.59 6.725,33.588 6.725,33.567 6.835,33.189 6.839,33.159 6.392,33.159
  region net NetCN6_1: 4.888,38.192 4.916,38.199 5.267,38.041 5.267,37.541 4.916,37.349 4.888,37.372
  region net RF_Pin: 6.178,31.1 6.178,31.179 6.377,31.754 6.832,31.754 7.031,31.193 7.031,31.1
  region net AGND: 5.47,3.779 5.475,3.784 5.475,5.192 6.053,5.192 6.702,6.1 7.018,6.1 7.119,5.999 7.119,5.678 7.023,5.581 6.953,5.581 6.782,5.411 6.782,3.272 6.491,2.98 5.812,2.98 5.48,3.312 5.48,3.779
  text "Layer" at 2.099,123.728 h1.52
  text "Name" at 12.511,123.728 h1.52
  text "Material" at 36.126,123.728 h1.52
  text "Thickness" at 57.964,123.728 h1.52
  text "Constant" at 74.47,123.728 h1.52
  text "Top Overlay" at 12.511,120.68 h1.52
  text "Top Solder" at 12.511,117.632 h1.52
  text "Solder Resist" at 36.126,117.632 h1.52
  text "0.018mm" at 57.964,117.632 h1.52
  text "3.2" at 74.47,117.632 h1.52
  text "1" at 2.099,114.584 h1.52
  text "Top Layer" at 12.511,114.584 h1.52
  text "0.035mm" at 57.964,114.584 h1.52
  text "Dielectric 1" at 12.511,111.536 h1.52
  text "FR-4" at 36.126,111.536 h1.52
  text "0.075mm" at 57.964,111.536 h1.52
  text "4.5" at 74.47,111.536 h1.52
  text "2" at 2.099,108.488 h1.52
  text "Internal 1" at 12.511,108.488 h1.52
  text "0.035mm" at 57.964,108.488 h1.52
  text "Dielectric 3" at 12.511,105.44 h1.52
  text "0.335mm" at 57.964,105.44 h1.52
  text "4.5" at 74.47,105.44 h1.52
  text "3" at 2.099,102.392 h1.52
  text "Internal 2" at 12.511,102.392 h1.52
  text "0.035mm" at 57.964,102.392 h1.52
  text "Dielectric 2" at 12.511,99.344 h1.52
  text "0.075mm" at 57.964,99.344 h1.52
  text "4.5" at 74.47,99.344 h1.52
  text "4" at 2.099,96.296 h1.52
  text "Bottom Layer" at 12.511,96.296 h1.52
  text "0.030mm" at 57.964,96.296 h1.52
  text "Bottom Solder" at 12.511,93.248 h1.52
  text "Solder Resist" at 36.126,93.248 h1.52
  text "0.018mm" at 57.964,93.248 h1.52
  text "4.2" at 74.47,93.248 h1.52
  text "Bottom Overlay" at 12.511,90.2 h1.52
Internal 1:
  pour cut-out: 11.29,35.436 ccw(c11.29,37.072) 12.447,35.915 14.738,38.206 cw(c16.534,36.41) 16.534,38.95 20.317,38.95 20.317,37.099 20.311,37.105 ccw(c17.184,35.523) 16.066,36.642 13.811,34.386 cw(c12.015,36.182) 12.015,33.642 11.307,33.642
  pour cut-out: 11.294,37.808 11.294,35.389 8.764,35.389 8.764,37.808
  pour cut-out: 5.541,29.62 7.663,29.62 7.663,33.017 7.663,33.778 6.203,33.778 5.541,33.013
  pour cut-out: 6.869,33.656 6.869,35.443 11.315,35.443 11.315,33.656
  pour cut-out: 2.896,39.075 5.279,39.075 5.279,36.521 2.896,36.521
  pour cut-out: 5.19,46.103 6.984,46.103 6.984,33.416 5.19,33.416
Internal 2:
  pour cut-out: 2.894,39.039 4.777,39.039 5.265,38.551 5.265,37.006 4.737,36.509 2.894,36.509
  pour cut-out: 11.296,37.809 11.296,35.981 10.808,35.493 9.35,35.493 8.766,36.02 8.766,37.809
  pour cut-out: 5.496,29.617 7.662,29.617 7.662,30.928 7.016,31.716 6.193,31.718 5.496,30.9

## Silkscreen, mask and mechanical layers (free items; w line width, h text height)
Top Overlay:
  lines w0.2: 0.99,31.329 0.99,-1.615 19.457,-1.615 19.457,-1.595 19.462,-1.595 19.462,31.359
  text "ST67W611M" at 7.973,15.149 h1
  text "B2415" at 9.065,0.557 h1.2
Bottom Overlay:
  text "J" at 6.531,17.327 h10
Top Solder:
  region: 11.407,35.771 11.407,38.978 10.716,38.978 10.716,35.771
  region: 9.398,35.76 9.398,38.967 8.707,38.967 8.707,35.76
  rectangle: 1.769,36.428 4.975,37.119
  rectangle: 1.749,38.448 4.956,39.14
M1-Board Shape:
  the board outline again, w0.2

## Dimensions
0.467,46.11 to 19.05,-2.54 on M3-Top Dimensions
